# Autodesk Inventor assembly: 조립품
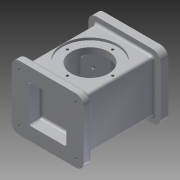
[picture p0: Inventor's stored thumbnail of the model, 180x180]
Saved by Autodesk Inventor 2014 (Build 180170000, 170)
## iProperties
Created: 2017-08
Part Number: 조립품
Document SubType Name: Assembly
Designer: user
Author: user
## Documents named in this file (2)
- C:\Users\user\Desktop\470808V1011\조립품.iam
- C:\Users\user\Desktop\470808V1011\본체.ipt
